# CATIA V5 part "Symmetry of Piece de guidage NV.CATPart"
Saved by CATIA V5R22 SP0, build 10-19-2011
Part number: Symmetry of Piece de guidage NV
Bounding box of the stored display mesh (mm): x 0 to 20, y -88 to -68, z 0 to 55
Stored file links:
  D:\CAO_PER_MODIF_2025\CAO_PER_pick&place_2024P\Symmetry of Piece de guidage NV.CATPart
  D:\CAO_PER_MODIF_2025\CAO_PER_pick&place_2024P\Sous_Ensemble_Flacon\Piece guidage L - QTE 1.CATPart
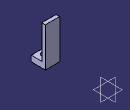
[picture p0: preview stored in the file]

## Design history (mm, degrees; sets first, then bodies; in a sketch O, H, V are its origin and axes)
Body1 (main body)
  Body2 "Corps du corps principal d'origine"
    Solid1: linked copy from another document
  Assemble1: tool Body2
